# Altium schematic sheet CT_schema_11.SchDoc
size 254 x 194 mm
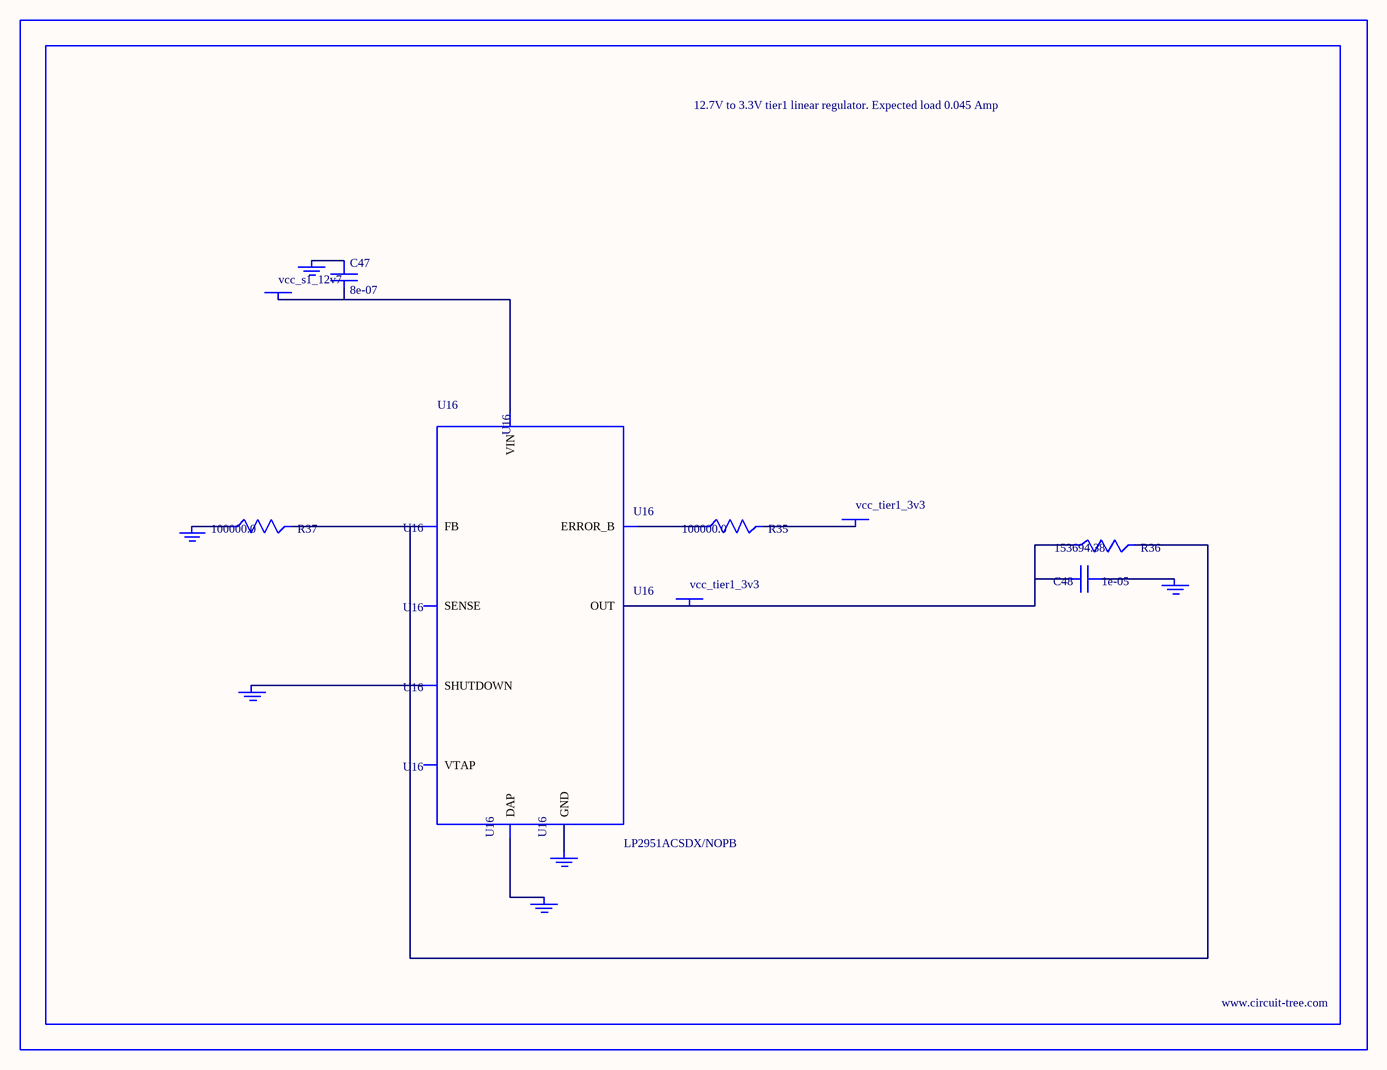
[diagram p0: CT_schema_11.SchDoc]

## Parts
BORDER10  (no value)
C47  8e-07  [R0603]
C48  1e-05  [C1210]
GND_INSTANCE_10_0  (no value)
GND_INSTANCE_10_1  (no value)
GND_INSTANCE_10_2  (no value)
GND_INSTANCE_10_3  (no value)
GND_INSTANCE_10_4  (no value)
GND_INSTANCE_10_5  (no value)
POWER_INSTANCE_10_0  vcc_tier1_3v3
POWER_INSTANCE_10_1  vcc_s1_12v7
POWER_INSTANCE_10_2  vcc_tier1_3v3
R35  100000.0  [R0603]
R36  153694.38  [R0603]
R37  100000.0  [R0603]
U16  LP2951ACSDX/NOPB  [WSON-8]

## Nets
NetC47_1: C47.1 GND_INSTANCE_10_3.0(GND)
NetC47_2: C47.2 POWER_INSTANCE_10_1.0(PWR) U16.8(VIN)
NetC48_1: C48.1 GND_INSTANCE_10_0.0(GND)
NetC48_2: C48.2 POWER_INSTANCE_10_2.0(PWR) R36.1 U16.1(OUT)
NetGND_INSTANCE_10_1_0: GND_INSTANCE_10_1.0(GND) U16.3(SHUTDOWN)
NetGND_INSTANCE_10_2_0: GND_INSTANCE_10_2.0(GND) R37.1
NetGND_INSTANCE_10_4_0: GND_INSTANCE_10_4.0(GND) U16.PAD(DAP)
NetGND_INSTANCE_10_5_0: GND_INSTANCE_10_5.0(GND) U16.4(GND)
NetPOWER_INSTANCE_10_0_0: POWER_INSTANCE_10_0.0(PWR) R35.2
NetR35_1: R35.1 U16.5(ERROR_B)
NetR36_2: R36.2 R37.2 U16.7(FB)

Not connected (* = marked no-connect by the designer): U16 2(SENSE) 6(VTAP)

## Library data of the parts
BORDER10 = BORDER_PAGE10
C47 = C47
C48 = GRM32DR61E106MA12L
GND_INSTANCE_10_0-GND_INSTANCE_10_5 = GND
POWER_INSTANCE_10_0-POWER_INSTANCE_10_2 = PWR
R35 R37 = RC0603JR-07100KL
R36 = R36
